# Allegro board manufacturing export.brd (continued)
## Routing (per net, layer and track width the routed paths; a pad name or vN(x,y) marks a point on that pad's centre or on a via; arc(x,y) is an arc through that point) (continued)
D1: length 116.7
  TOP w0.127: U15.3 10.22,60.12 9.46,59.36 9.46,53.52 9.72,53.26 13.93,53.26 v1(16.45,55.78) 16.45,71.36 13.08,74.73 U18.3 ; v1(45.2,54.75) 45.16,54.79 U11.100
  BOTTOM w0.127: J1.27 45.4,10.02 45.4,18.58 45.07,18.91 45.07,54.01 45.2,54.14 v1(45.2,54.75) 45.2,56.02 44.2,57.02 40.64,57.02 40.58,56.96 24.07,56.96 22.89,55.78 v1(16.45,55.78)
D2: length 111.3
  TOP w0.127: U15.4 v1(11.62,58.85) ; U18.4 v1(11.61,73.46) ; U11.99 v1(45.82,57.45)
  BOTTOM w0.127: v1(11.61,73.46) 8.72,70.57 8.72,61.75 v1(11.62,58.85) 11.62,58.24 12.98,56.88 21.87,56.88 22.2,57.21 39.56,57.21 39.8,57.45 v1(45.82,57.45) 45.82,40.11 45.33,39.61 45.33,24.75 45.66,24.42 45.66,8.88 44.89,8.12 43.88,8.12 43.5,8.5 43.5,10.66 J1.28
D3: length 111.8
  TOP w0.127: U18.5 14.43,72.19 15.95,70.66 v1(15.95,57.82) ; v1(45.2,58.22) 46.72,58.22 47.8,57.14 U11.96 47.8,51.33 v1(50.52,48.62) ; U15.5 v1(13.37,57.58)
  BOTTOM w0.127: v1(50.52,48.62) 50.52,32.49 49.95,31.92 49.95,13.83 50.48,13.3 50.48,8.62 49.97,8.12 47.94,8.12 J1.29 ; v1(13.37,57.58) 15.71,57.58 v1(15.95,57.82) 17.3,59.17 38.54,59.17 39.5,58.22 v1(45.2,58.22)
D4: length 103.6
  TOP w0.127: U15.6 13.02,56.31 14.68,57.98 v1(14.68,58.59) 14.68,67.72 11.48,70.92 U18.6 ; U11.95 v1(48.46,53.15)
  BOTTOM w0.127: 47.64,53.15 46.99,52.5 J1.30 ; 47.64,53.15 v1(48.46,53.15) ; 47.64,53.15 47.64,56.88 45.1,59.42 16.54,59.42 15.7,58.59 v1(14.68,58.59)
D5: length 114
  TOP w0.127: U11.94 v1(49.12,53.89) ; U15.7 13.93,55.04 15.2,56.31 v1(15.2,59.68) 15.2,69.68 13.34,71.55 9.87,71.55 9.72,71.4 9.72,70.09 10.16,69.65 U18.7
  BOTTOM w0.127: v1(15.2,59.68) 47.76,59.68 47.97,59.47 47.97,54.43 48.51,53.89 v1(49.12,53.89) 49.12,21.2 48.58,20.65 48.58,10.02 J1.31
D6: length 106.1
  TOP w0.127: U11.93 49.78,57.9 v1(49.72,57.96) ; U15.8 10.16,53.77 9.72,54.22 9.72,58.09 9.84,58.22 11.87,58.22 12.5,58.84 v1(12.5,59.65) 12.5,67.51 11.63,68.38 U18.8
  BOTTOM w0.127: v1(12.5,59.65) 13.02,60.17 48.12,60.17 49.72,58.57 v1(49.72,57.96) 49.72,51.63 49.53,51.43 J1.32
D7: length 113.6
  TOP w0.127: U11.92 v1(50.44,57.44) ; U18.9 10.79,67.11 11.37,66.54 11.37,62.18 11.21,62.03 v1(9.53,62.03) 8.95,61.46 8.95,52.82 9.27,52.5 U15.9
  BOTTOM w0.127: J1.33 51.12,10.02 51.12,23.76 51.6,24.24 51.6,50.72 50.44,51.88 v1(50.44,57.44) 50.44,59.92 49.68,60.68 10.87,60.68 v1(9.53,62.03)
D8: length 114.6
  TOP w0.127: U17.2 19.62,37.9 18.38,36.65 18.38,29.31 19.19,28.5 v1(21.01,28.5) ; v1(51.87,15.88) 51.85,15.89 15.86,15.89 14,17.75 14,18.78 14.25,19.04 16.51,19.04 16.52,19.05 17.17,19.05 17.67,18.55 18.19,18.55 18.43,18.8 18.57,18.8 18.89,18.8 18.95,18.86 19.96,18.86 19.98,18.85 v1(20.75,18.85) ; U14.2 v1(21.01,22.66) ; U11.90 v1(51.77,52.37)
  BOTTOM w0.127: v1(20.75,18.85) 21.01,19.1 v1(21.01,22.66) v1(21.01,28.5) ; v1(51.77,52.37) 51.87,52.27 51.87,42.15 51.85,42.14 51.85,41.73 51.87,41.72 51.87,28.6 51.85,28.59 51.85,28.18 51.87,28.17 v1(51.87,15.88) 51.87,12.88 52.07,12.67 J1.34
D9: length 100.6
  TOP w0.127: v1(53.54,23.8) 20.76,23.8 20.76,23.93 ; v1(54.04,48.58) 53.02,48.58 52.43,49.17 U11.89 ; U14.3 20.76,23.93 ; 20.76,23.93 20.76,25.6 20.54,25.83 19.27,25.83 18.12,26.97 18.12,37.67 19.62,39.17 U17.3
  BOTTOM w0.127: v1(54.04,48.58) 54.04,24.3 v1(53.54,23.8) 53.54,10.13 J1.35
D10: length 106.4
  TOP w0.127: U14.4 v1(18.87,25.2) 17.87,26.2 17.87,39.31 19,40.44 U17.4 ; v1(54.61,49.11) 54,49.11 53.09,50.03 U11.88 ; v1(18.87,18.05) v1(54.61,18.05)
  BOTTOM w0.127: v1(54.61,49.11) v1(54.61,18.05) J1.36 ; v1(18.87,18.05) 18.87,18.81 18.91,18.84 18.91,19.48 18.87,19.52 v1(18.87,25.2)
D11: length 109.7
  TOP w0.127: U14.5 v1(21.5,26.47) ; U17.5 v1(18.87,41.71) ; U11.87 v1(53.75,50.37) ; v1(55.64,19.04) 55.64,18.85 v1(21.59,18.85)
  BOTTOM w0.127: J1.37 55.64,10.58 v1(55.64,19.04) 55.64,49.09 54.36,50.37 v1(53.75,50.37) ; v1(21.59,18.85) 21.59,21.09 21.5,21.09 21.5,21.59 21.59,21.68 21.59,26.47 v1(21.5,26.47) 21.5,39.08 v1(18.87,41.71)
D12: length 104.8
  TOP w0.127: v1(18.87,27.74) U14.6 20.95,27.74 22.25,26.44 22.25,25.32 23.52,24.05 49.06,24.05 49.56,24.55 v1(56.65,24.55) ; U11.86 v1(54.41,51.65) ; U17.6 v1(17.12,42.98)
  BOTTOM w0.127: v1(17.12,42.98) 17.12,29.49 v1(18.87,27.74) ; J1.38 57.15,24.05 v1(56.65,24.55) 55.89,25.31 55.89,50.77 55.02,51.65 v1(54.41,51.65)
D13: length 108.2
  TOP w0.127: U14.7 21.46,29.01 21.79,29.34 21.79,41.68 22.01,41.9 ; v1(43.93,46.32) 53.61,46.32 56.15,48.86 v1(56.15,52.71) 56.39,52.95 U11.83 ; v1(22.01,43.21) 22.01,41.9 ; 22.01,41.9 v1(36.87,41.9) ; v1(21.01,43.99) 20.75,44.25 U17.7
  BOTTOM w0.127: J1.39 58.1,10.66 58.1,24.61 56.15,26.57 v1(56.15,52.71) ; v1(22.01,43.21) 22.01,43.81 21.83,43.99 v1(21.01,43.99) ; v1(43.93,46.32) 39.51,41.9 v1(36.87,41.9)
D14: length 124.2
  TOP w0.127: v1(36.23,62.62) 36.23,47.8 33.95,45.52 21.53,45.52 ; v1(51.45,58.97) 55.52,58.97 v1(57.05,57.44) U11.82 ; 21.53,45.52 U17.8 ; 21.53,45.52 v1(21.53,44.68) ; U14.8 v1(21.01,30.28)
  BOTTOM w0.127: v1(57.05,57.44) 57.05,41.87 58.36,40.56 58.36,12.94 J1.40 ; v1(21.53,44.68) 20.41,44.68 17.87,42.14 17.87,32.8 20.4,30.28 v1(21.01,30.28) ; v1(51.45,58.97) 51.45,60.08 48.91,62.62 v1(36.23,62.62)
D15: length 127
  TOP w0.127: U14.9 20.88,31.55 21.02,31.69 21.02,43.23 20.64,43.61 19.24,43.61 19,43.85 19,46.16 19.62,46.79 U17.9 v1(34.32,46.79) ; v1(43.93,56.53) 43.93,58.25 46.22,60.54 v1(56.1,60.54) 57.71,58.93 U11.81
  BOTTOM w0.127: v1(43.93,56.53) 35.84,56.53 34.32,55 v1(34.32,46.79) ; J1.41 63.18,10.02 63.18,51.98 58.55,56.62 58.55,59.61 57.62,60.54 v1(56.1,60.54)
DATA0: length 76.9
  TOP w0.127: U15.18 20.88,60.12 22.02,61.27 22.02,74.73 ; U8.6 73.91,71.87 71.88,69.84 69.79,69.84 69.15,70.47 67.5,70.47 65.98,72 65.72,72 64.19,73.53 64.19,73.58 64.14,73.63 64.14,76.39 63.69,76.83 37.44,76.83 36.83,76.23 36.83,75.41 U16.13 31.37,75.36 30.73,74.73 22.02,74.73 ; 22.02,74.73 U18.18
DATA1: length 74.7
  TOP w0.127: v1(22.52,73.46) 22.52,60.12 21.25,58.85 U15.17 ; U8.7 68.01,70.79 67.25,71.55 67.25,73.27 65.79,74.73 65.53,74.73 64.57,75.69 64.57,76.32 63.8,77.09 36.53,77.09 36.28,77.33 v1(35.67,77.33) 35.04,77.33 U16.14 ; U18.17 v1(21.01,73.46)
  BOTTOM w0.127: v1(35.67,77.33) 27,77.33 23.13,73.46 v1(22.52,73.46) 22.09,73.03 21.44,73.03 v1(21.01,73.46)
DATA2: length 86.1
  TOP w0.127: U8.3 69.93,75.87 69.62,75.56 67.81,75.56 66.99,76.38 66.99,79.24 66.74,79.49 59.93,79.49 58.74,78.3 33.66,78.3 33.66,78.04 ; 19.11,72.19 19.11,70.43 19.27,70.28 20.64,70.28 20.76,70.15 20.76,67.89 20.61,67.74 19.11,67.74 18.61,67.23 18.61,57.9 18.92,57.58 U15.16 ; 19.11,72.19 U18.16 ; 19.11,72.19 19.05,72.19 18.41,72.82 18.41,76.43 18.75,76.76 24.16,76.76 25.44,78.04 27.81,78.04 27.94,77.91 27.94,76.54 28.28,76.2 28.78,76.2 29.21,76.63 29.21,77.89 29.36,78.04 33.66,78.04 ; U16.15 33.66,78.04
DATA3: length 97.9
  TOP w0.127: U8.4 74.87,73.65 74.87,69.08 74.36,68.57 73.22,68.57 72.58,69.2 70.42,69.2 69.79,68.57 67.75,68.57 66.74,69.58 65.58,69.58 63.3,71.87 63.3,75.4 62.54,76.16 38.91,76.16 v1(38.84,76.09) ; 21.16,70.92 21.16,66.99 20.64,66.47 19.24,66.47 19.11,66.34 19.11,58.37 19.14,58.34 21.03,58.34 21.39,57.99 21.39,56.82 20.88,56.31 U15.15 ; 21.16,70.92 U18.15 ; 21.16,70.92 21.16,70.92 21.16,72.19 20.53,72.82 19.27,72.82 18.85,73.24 18.85,76.2 19.15,76.5 25.68,76.5 26.53,75.65 29.84,75.65 ; 29.84,75.65 U16.18 ; 29.84,75.65 33.13,75.65 v1(33.63,76.15)
  BOTTOM w0.127: v1(38.84,76.09) 38.77,76.15 v1(33.63,76.15)
DATA4: length 98.3
  TOP w0.127: 18.12,69.65 18.12,76.77 19.14,77.79 24.45,77.79 25.2,78.54 28.57,78.54 28.57,78.54 ; 18.12,69.65 18.12,68.89 18.1,68.86 18.1,54.28 19.24,53.14 20.61,53.14 20.76,53.29 20.76,54.6 20.32,55.04 U15.14 ; 18.12,69.65 U18.14 ; 28.57,78.54 U16.19 ; 28.57,78.54 28.57,78.55 57.21,78.55 58.41,79.74 66.84,79.74 67.31,79.28 67.31,76.63 67.94,76 69.44,76 70.27,76.82 71.82,76.82 72.59,76.05 72.59,73.09 71.56,72.06 U7.6
DATA5: length 73.7
  TOP w0.127: U7.7 63.7,72.87 63.7,76.31 63.44,76.58 38.42,76.58 38.1,76.26 v1(38.1,75.65) ; U18.13 v1(18.85,68.38) 18.37,68.38 18.35,68.36 18.35,55.04 19.62,53.77 U15.13 ; U16.20 v1(27.3,76.15)
  BOTTOM w0.127: v1(27.3,76.15) 27.3,75.65 ; 27.3,75.65 v1(38.1,75.65) ; 27.3,75.65 20.03,68.38 v1(18.85,68.38)
DATA6: length 113.2
  TOP w0.127: v1(68.5,79.36) 67.87,80 56.63,80 55.65,79.02 v1(24.16,79.02) 18.88,79.02 17.11,77.24 17.11,53.77 18.38,52.5 U15.12 20.88,52.5 21.27,52.9 21.27,54.94 20.54,55.68 19.27,55.68 19.05,55.89 19.05,56.64 19.35,56.95 20.61,56.95 20.95,57.29 20.95,57.79 20.65,58.09 18.88,58.09 18.86,58.12 18.86,66.97 19,67.11 U18.12 ; U16.21 v1(24.16,75.36)
  BOTTOM w0.127: v1(24.16,75.36) v1(24.16,79.02) ; U7.3 68.52,75.87 69.28,76.63 69.28,78.59 v1(68.5,79.36)
DATA7: length 91.1
  TOP w0.127: U15.11 20.88,51.23 23.05,53.4 v1(23.05,74.09) U16.22 ; v1(21.53,74.09) 21.53,66.48 20.88,65.84 U18.11 ; v1(37.97,77.58) 38.58,77.58 38.82,77.34 65.84,77.34 66.74,76.44 66.74,75.12 67.26,74.6 U7.4
  BOTTOM w0.127: v1(37.97,77.58) 36.04,79.51 23.81,79.51 23.05,78.75 v1(23.05,74.09) v1(21.53,74.09)
DATA8: length 105.5
  TOP w0.127: U6.6 72.39,27.36 72.39,21.82 70.1,19.53 35.18,19.53 34.92,19.28 21.86,19.28 21.8,19.34 21.38,19.34 21.32,19.28 21.02,19.28 20.96,19.34 20.55,19.34 20.48,19.28 19.01,19.28 18.78,19.05 v1(17.98,19.05) ; v1(18.33,21.4) 14.01,21.4 11.48,23.93 U14.18 ; U13.13 v1(18.33,23.29) ; U17.18 v1(9.47,39.17)
  BOTTOM w0.127: v1(17.98,19.05) 17.98,21.06 v1(18.33,21.4) v1(18.33,23.29) 18.33,25.69 14.47,29.55 11.93,29.55 8.98,32.5 8.98,38.67 v1(9.47,39.17)
DATA9: length 117
  TOP w0.127: U13.14 27.3,21.82 27.23,21.89 v1(14.49,21.89) 14.49,23.67 12.97,25.2 U14.17 ; U17.17 v1(11.61,40.44) ; U6.7 72.83,28.56 72.83,21.2 70.05,18.41 61.72,18.41 61.59,18.54 61.18,18.54 61.05,18.41 54.94,18.41 54.82,18.54 54.4,18.54 54.28,18.41 21.86,18.41 21.8,18.35 20.55,18.35 20.48,18.41 19.2,18.41 19.08,18.54 18.67,18.54 18.43,18.3 17.46,18.3 17.22,18.54 v1(14.49,18.54)
  BOTTOM w0.127: v1(11.61,40.44) 9.99,40.44 8.47,38.91 8.47,26.45 11.01,23.91 12.47,23.91 v1(14.49,21.89) v1(14.49,18.54)
DATA10: length 130
  TOP w0.127: U17.16 11.48,41.71 12.1,41.08 v1(12.1,28.52) 12.1,27.09 11.48,26.47 U14.16 ; v1(14.99,20.85) 15.6,20.85 15.84,20.61 28,20.61 28.57,21.18 U13.15
  BOTTOM w0.127: U6.3 75.12,23.36 75.12,9.64 72.58,7.1 16.76,7.1 14.99,8.88 v1(14.99,20.85) 14.99,25.64 v1(12.1,28.52)
DATA11: length 94.5
  TOP w0.127: U6.4 69.15,23.61 67.22,23.61 66.47,24.36 64.08,24.36 62.48,22.76 33.32,22.76 32.84,22.28 32.84,22.25 32.38,21.79 U13.18 32.38,20.99 31.75,20.36 10.22,20.36 9.72,20.87 9.72,25.96 ; U17.15 10.79,42.98 11.23,43.41 12.04,43.41 12.1,43.35 12.1,42.21 12.61,41.71 12.61,26.47 11.98,25.83 10.1,25.83 9.97,25.96 9.72,25.96 ; 9.72,25.96 9.72,26.91 U14.15
DATA12: length 91.4
  TOP w0.127: U17.14 9.6,44.25 8.98,43.62 8.98,31.65 9.72,30.91 11.21,30.91 11.37,30.76 11.37,29.83 U14.14 9.6,29.01 9.46,28.87 9.46,20.76 9.58,20.65 9.58,20.64 10.05,20.17 10.05,20.17 10.12,20.1 31.92,20.1 31.93,20.12 33.27,20.12 33.66,20.5 U13.19 34.48,22.26 v1(64.71,22.26)
  BOTTOM w0.127: v1(64.71,22.26) 64.71,27.29 U5.6
DATA13: length 99.1
  TOP w0.127: 34.92,20.61 U13.20 ; 34.92,20.61 34,19.68 12.9,19.68 11.86,18.64 9.53,18.64 9.09,19.08 9.09,30.16 9.21,30.28 ; 34.92,20.61 v1(61.59,20.61) ; U5.7 62.66,29.64 v1(61.59,28.57) ; 9.21,30.28 8.95,30.28 8.47,30.76 8.47,44.39 9.6,45.52 U17.13 ; 9.21,30.28 U14.13
  BOTTOM w0.127: v1(61.59,20.61) v1(61.59,28.57)
DATA14: length 82.3
  TOP w0.127: U5.3 67.03,24.56 66.83,24.77 61.16,24.77 59.69,23.29 U13.21 26.87,23.29 25.73,22.15 18.53,22.15 13.37,27.3 v1(13.37,31.55) 13.37,44.89 11.48,46.79 U17.12 ; U14.12 v1(11.61,31.55)
  BOTTOM w0.127: v1(11.61,31.55) v1(13.37,31.55)
DATA15: length 93.4
  TOP w0.127: U5.4 46.27,25.83 45,24.56 U13.22 26.76,24.56 26.12,25.2 25.01,25.2 24.88,25.07 v1(23.67,25.07) ; U14.11 v1(9.47,32.82) ; U17.11 v1(14.12,48.06)
  BOTTOM w0.127: 14.12,45.17 21.89,45.17 23.67,43.4 v1(23.67,25.07) ; 14.12,45.17 v1(14.12,48.06) ; 14.12,45.17 14.12,37.47 v1(9.47,32.82)
HLDA: length 169.3
  TOP w0.127: U2.2 57.78,100.76 ; 57.78,100.76 57.78,101.02 58.17,101.4 64.39,101.4 65.02,102.03 U20.1 ; 57.78,100.76 v1(54.33,100.76) 49.63,100.76 49.12,101.27 U3.2 ; U1.2 47.5,88.7 48.01,89.2 53.82,89.2 v1(54.33,88.7) U4.2 ; v1(39.13,52.5) U11.3 43.8,52.5 44.42,53.12 44.42,58.2 45.95,59.73 v1(54.33,59.73) ; U19.13 v1(54.33,66.47)
  BOTTOM w0.127: v1(39.13,52.5) 37.26,52.5 35.74,50.98 35.74,9.13 34.72,8.12 18.48,8.12 17.59,9 17.59,10.53 J1.6 ; v1(54.33,59.73) v1(54.33,66.47) 54.33,67.08 54.11,67.3 54.11,87.87 54.33,88.09 v1(54.33,88.7) v1(54.33,100.76)
M_IO: length 78.6
  TOP w0.127: v1(55.14,44.58) 49.45,44.58 44.17,39.29 U11.23 ; U19.11 54.61,63.54 55.85,62.29 57.19,62.29 58.32,61.16 58.32,54.84 56.9,53.42 56.9,46.56 56.16,45.82 v1(55.14,45.82) ; v1(55.14,15.21) 61.16,15.21 J1.44
  BOTTOM w0.127: v1(55.14,45.82) v1(55.14,44.58) v1(55.14,15.21)
MUXSOL: length 54.9
  TOP w0.127: U3.14 v1(52.82,100) 57.28,100 57.4,100.13 59.82,100.13 60.45,99.49 U2.14 ; U1.14 v1(53.34,87.43) 53.85,87.93 60.2,87.93 60.71,87.43 U4.14 ; v1(53.34,72.62) U19.20
  BOTTOM w0.127: v1(52.82,100) 52.82,87.95 v1(53.34,87.43) v1(53.34,72.62)
PCLK: length 184.7
  TOP w0.127: v1(47.19,71.55) U19.27 42.72,71.55 41.71,70.54 41.71,69.74 41.73,69.71 41.73,69.3 41.71,69.28 41.71,66.27 40.01,64.57 38.33,64.57 36.83,63.07 36.83,47.62 34.09,44.88 28.47,44.88 27.77,44.18 21.5,44.18 21.5,30 v1(21.01,29.5) ; U10.6 17.78,87.43 18.8,88.44 18.8,93.52 20.32,95.05 22.86,95.05 22.86,96.52 23.5,96.52 23.5,92.71 23.93,92.71 23.93,96.52 24.56,96.52 24.56,92.71 24.97,92.71 24.97,96.52 25.4,96.52 25.4,95.05 27.71,95.05 27.94,95.28 27.94,96.95 28.57,96.95 28.57,92.71 29.01,92.71 29.01,96.95 29.64,96.95 29.64,92.71 30.28,92.71 30.28,96.95 31.11,96.95 31.11,94.41 U12.13 35.42,94.41 35.65,94.18 35.65,88.24 35.83,88.06 39.75,88.06 40.03,87.78 40.03,81.86 40.18,81.71 45.67,81.71 45.75,81.64 v1(46.74,81.64)
  BOTTOM w0.127: J1.7 20.12,9.07 20.26,9.21 20.26,29.36 20.4,29.5 v1(21.01,29.5) ; v1(46.74,81.64) 46.74,72.01 v1(47.19,71.55)
RA0: length 28.7
  TOP w0.127: U12.3 38.35,95.68 37.73,96.3 37.73,97.32 37.87,97.46 42.51,97.46 44.41,95.55 45.97,95.55 46.1,95.68 49.91,95.68 50.04,95.55 56.16,95.55 56.67,95.05 60.07,95.05 60.71,95.68 U2.11
RA1: length 39.7
  TOP w0.127: U4.5 58.17,84.89 60.2,86.92 63.53,86.92 63.93,87.33 63.93,88.93 63.53,89.33 57.4,89.33 57.28,89.46 45.72,89.46 45.59,89.33 44.37,89.33 43.23,90.47 43.23,94.41 40.69,96.95 U12.4
RA2: length 27.1
  TOP w0.127: v1(42.23,82.85) 47.98,82.85 48.74,83.62 U1.11 ; U12.5 v1(42.23,98.22)
  BOTTOM w0.127: v1(42.23,82.85) v1(42.23,98.22)
RA3: length 13.8
  TOP w0.127: U3.11 48.39,96.19 47.12,97.46 47.12,98.48 46.35,99.24 39.87,99.24 39.61,99.49 U12.6
RA4: length 20.8
  TOP w0.127: U12.11 35.86,96.95 37.77,95.05 39.78,95.05 41.81,93.01 41.81,85.52 42.44,84.89 U1.5
RA5: length 12.1
  TOP w0.127: U12.10 35.31,98.22 35.81,97.71 45.28,97.71 U3.5
RA6: length 26.4
  TOP w0.127: U2.5 48.11,96.95 47.42,97.64 47.42,98.88 46.81,99.49 40.01,99.49 39.37,100.13 37.67,100.13 37.04,99.49 U12.9
RA7: length 52.1
  TOP w0.127: U4.11 v1(63.87,83.62) ; v1(61.46,87.92) 60.85,87.92 60.58,88.19 50.67,88.19 50.55,88.06 48.13,88.06 46.23,86.16 46.23,84.63 45.85,84.25 42.11,84.25 41.05,85.32 41.05,91.71 39.61,93.14 U12.1 v1(36.42,93.14) ; U12.8 v1(36.42,100.76)
  BOTTOM w0.127: v1(61.46,87.92) 62.06,87.92 63.87,86.12 v1(63.87,83.62) ; v1(36.42,100.76) v1(36.42,93.14)
RA8: length 12.6
  TOP w0.127: U20.11 73.6,97.97 71.22,97.97 69.57,96.32 65.79,96.32 63.88,94.41 U2.10
RA9: length 28.5
  TOP w0.127: U20.10 74.73,96.08 74.73,88.24 72.01,85.52 61.34,85.52 60.96,85.14 60.96,84.12 60.45,83.62 U4.6
RA10: length 31.6
  TOP w0.127: U1.10 53.47,82.35 55.5,84.38 59.18,84.38 59.94,85.14 59.94,85.57 61.04,86.66 67.37,86.66 72.52,91.81 72.52,95.29 72.91,95.68 U20.9
RA11: length 33.7
  TOP w0.127: U20.8 73.86,94.41 v1(73.86,92.71) 68.52,87.36 ; U3.10 54.81,94.92 57.1,92.63 v1(72.02,92.63)
  BOTTOM w0.127: v1(73.86,92.71) 72.02,92.71 v1(72.02,92.63)
RA12: length 36.9
  TOP w0.127: U20.3 v1(66.41,99.49) ; v1(56.1,85.65) 48.12,85.65 46.09,83.62 U1.6
  BOTTOM w0.127: v1(56.1,85.65) 56.1,96.8 58.79,99.49 v1(66.41,99.49)
RA13: length 27.3
  TOP w0.127: v1(47.62,99.99) 48.37,99.24 54.61,99.24 54.86,98.98 62.23,98.98 62.36,98.86 66.04,98.86 66.67,98.22 U20.4 ; U3.6 v1(46.62,96.19)
  BOTTOM w0.127: v1(46.62,96.19) 47.62,97.19 v1(47.62,99.99)
RA14: length 11.6
  TOP w0.127: U20.5 64.9,96.95 64.26,96.32 60.33,96.32 59.69,95.68 U2.6
RA15: length 30.1
  TOP w0.127: 75.77,97.59 75.77,87.69 ; 75.77,97.59 73.13,97.59 71.22,95.68 U20.6 ; 75.77,97.59 75.77,100.56 75.56,100.76 U20.13 ; 70.42,82.35 U4.10
RASL: length 73.1
  TOP w0.127: U5.9 U6.9 ; U8.9 U7.9 ; U19.25 46.99,73.86 51.21,69.65 56.96,69.65 v1(59.31,67.3)
  BOTTOM w0.127: U7.9 64.83,67.3 v1(59.31,67.3) ; U6.9 75.12,33.39 75.12,67.23 74.1,68.25 U8.9
RDYL: length 96
  TOP w0.127: v1(52.84,48.08) 46.48,48.08 44.7,49.86 U11.7 41.16,49.86 38.62,47.32 38.62,42.42 36.59,40.39 v1(22.54,40.39) ; U19.21 v1(52.07,71.6)
  BOTTOM w0.127: J1.9 22.54,10.02 v1(22.54,40.39) ; v1(52.07,71.6) 52.84,70.83 v1(52.84,48.08)
REF: length 70.1
  TOP w0.127: v1(44.78,62.13) 45.26,62.13 U19.5 ; v1(37.36,51.84) v1(37.36,62.13) ; U10.7 v1(17.63,88.7) ; U11.4 v1(38.61,51.84)
  BOTTOM w0.127: v1(44.78,62.13) v1(37.36,62.13) 24.47,62.13 18.72,67.88 18.64,67.88 18.35,68.17 18.35,68.25 17.63,68.97 v1(17.63,88.7) ; v1(38.61,51.84) v1(37.36,51.84)
RESET: length 151.2
  TOP w0.127: U21.12 v1(18.03,95.68) 16.76,94.41 U9.9 ; U11.33 v1(46.48,31.23) ; U19.7 49.53,63.54 47.24,61.25 42.68,61.25 ; 42.68,61.25 v1(42.68,58.92) ; 42.68,61.25 v1(42.18,61.25) ; J1.8 21.02,13.58 33.36,13.58 33.37,13.59 45.36,13.59 v1(46.48,14.71)
  BOTTOM w0.127: v1(18.03,95.68) 16.38,94.03 16.38,68.54 23.67,61.25 v1(42.18,61.25) ; v1(46.48,14.71) v1(46.48,31.23) 46.48,57.65 45.21,58.92 v1(42.68,58.92)
RESETL: length 8.2
  TOP w0.127: U9.8 15.49,93.14 14.81,92.46 14.81,86.84 15.49,86.16 U10.5
ROMOEL: length 73.8
  TOP w0.127: U19.26 43.04,72.82 v1(40.5,70.28) ; v1(25.21,51.23) 25.2,51.23 23.86,52.57 23.86,69.71 24.43,70.28 U16.25 v1(34.94,70.28) ; v1(28.57,29.65) 29.86,28.37 U13.25
  BOTTOM w0.127: v1(28.57,29.65) 25.21,33.02 v1(25.21,51.23) ; v1(40.5,70.28) v1(34.94,70.28)
UNNAMED_1_OSC_I31_B: length 4.6
  TOP w0.127: v1(36.63,43.81) 35.79,42.98 Y1.8
  BOTTOM w0.127: R1.1 37.92,42.72 36.83,43.81 v1(36.63,43.81)
W_R: length 202.3
  TOP w0.127: U18.1 9.6,77.27 8.98,76.64 8.98,62.66 ; v1(28.14,42.55) 29.84,44.25 34.29,44.25 37.9,47.85 37.9,53.95 38.77,54.83 40.04,54.83 41.31,56.1 41.31,61.24 41.82,61.75 43.97,61.75 44.26,62.04 44.26,64.82 44.64,65.2 U19.4 ; v1(28.14,41.27) v1(22.86,41.27) ; U11.25 v1(40.96,37.97) v1(23.04,37.97) ; 8.98,62.66 8.7,62.38 8.7,51.69 11.32,49.07 14.43,49.07 15.63,47.87 15.63,43.68 v1(18.36,40.94) 18.97,40.94 19.1,41.07 20.61,41.07 20.76,40.92 20.76,37.07 20.32,36.63 U17.1 ; 8.98,62.66 U15.1 ; U14.1 v1(22,21.39)
  BOTTOM w0.127: 21.78,41.27 21.78,41.91 21.49,42.2 18.62,42.2 18.36,41.95 v1(18.36,40.94) ; 21.78,41.27 v1(22.86,41.27) 23.04,41.27 v1(23.04,37.97) ; 21.78,41.27 21.78,34.04 22,33.82 v1(22,21.39) ; v1(40.96,37.97) 40.96,8.62 41.97,7.61 65.85,7.61 J1.45 ; v1(28.14,41.27) v1(28.14,42.55)
WEL: length 68.4
  TOP w0.127: U19.18 59.71,72.82 v1(60.4,72.13) ; U5.8 U6.8 ; U8.8 U7.8
  BOTTOM w0.127: U6.8 74.36,30.91 75.63,32.18 75.63,68.87 74.98,69.52 U8.8 ; U7.8 63.01,69.52 v1(60.4,72.13)

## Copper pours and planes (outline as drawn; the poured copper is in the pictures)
GND on GND: 7.62,5.51 7.62,104.57 76.2,104.57 76.2,5.51
VCC on VCC: 7.62,5.51 7.62,104.57 76.2,104.57 76.2,5.51
